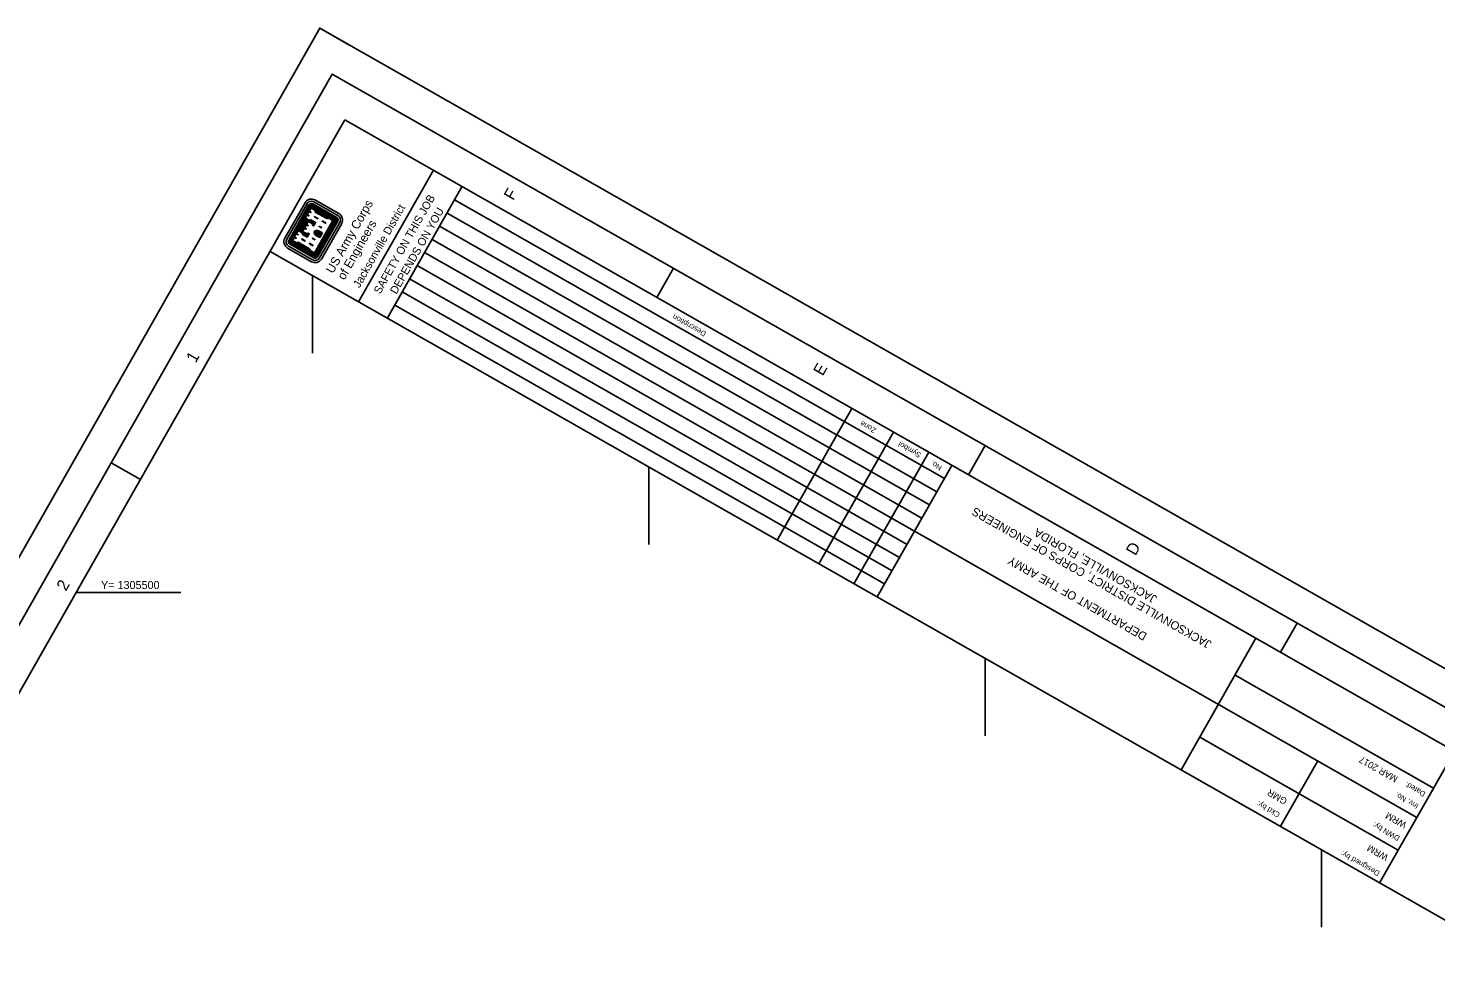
# Model space of a CAD drawing. Extents: x 517335 to 522466, y 1300833 to 1306339.
# Drawn here: x 519077 to 521170, y 1304957 to 1306339 of the extents above; entities that cross this region are included whole.
import ezdxf

# ---------------------------------------------------------------- set-up
doc = ezdxf.new("R2010")
doc.units = 0
for name, color, linetype in [('G-ANNO-NPLT', 7, 'Continuous'), ('G-ANNO-TEXT-DRWG', 7, 'Continuous'), ('G-ANNO-TEXT-LOGO', 7, 'Continuous'), ('G-ANNO-TEXT-PROJ', 7, 'Continuous'), ('G-ANNO-TEXT-TTLB', 7, 'Continuous'), ('G-ANNO-TTLB', 7, 'Continuous'), ('V-TOPO-COOR-STAT', 7, 'Continuous')]:
    doc.layers.add(name, color=color, linetype=linetype)

msp = doc.modelspace()

# ---------------------------------------------------------------- linework, layer by layer
at = {"layer": 'G-ANNO-NPLT'}
msp.add_lwpolyline([(517335, 1302514.1), (519510.6, 1306338.6), (522465.8, 1304657.4), (520290.3, 1300833)], close=True, dxfattribs=at)
msp.add_lwpolyline([(519554, 1306313.8), (519510.6, 1306338.6), (519485.8, 1306295.1)], dxfattribs=at)
at = {"layer": 'G-ANNO-TEXT-LOGO'}
for p, q in [((519488.9, 1306079.2), (519458.8, 1306026.4)), ((519461.6, 1306024.8), (519491.7, 1306077.6)), ((519494.6, 1306076), (519464.6, 1306023.1)), ((519495.4, 1306075.5), (519465.3, 1306022.7)), ((519496.2, 1306075.1), (519466.1, 1306022.2)), ((519496.9, 1306074.7), (519466.8, 1306021.8)), ((519497.7, 1306074.2), (519467.6, 1306021.4)), ((519497.6, 1306072.9), (519532.2, 1306053.2)), ((519498, 1306073.6), (519533.4, 1306053.5)), ((519498.4, 1306074.4), (519534.1, 1306054.1)), ((519498.9, 1306075.1), (519534.5, 1306054.9)), ((519499.3, 1306075.8), (519534.9, 1306055.6)), ((519499.7, 1306076.6), (519535.4, 1306056.3)), ((519500.2, 1306077.4), (519535.8, 1306057.1)), ((519501.8, 1306080.4), (519537.5, 1306060.1)), ((519539.1, 1306063), (519503.5, 1306083.2)), ((519504.9, 1306067.9), (519523, 1306057.6)), ((519505.1, 1306066.7), (519521.7, 1306057.3)), ((519478.7, 1306039.3), (519487.9, 1306055.5)), ((519479.5, 1306038.9), (519488.7, 1306055)), ((519480.2, 1306038.5), (519489.4, 1306054.6)), ((519481, 1306038), (519490.2, 1306054.2)), ((519481.8, 1306037.6), (519491, 1306053.8)), ((519482.5, 1306037.2), (519491.7, 1306053.4)), ((519483.2, 1306036.7), (519492.4, 1306052.9)), ((519532.2, 1306053.2), (519503.3, 1306002.4)), ((519533.4, 1306053.5), (519503.7, 1306001.3)), ((519534.3, 1306053.4), (519504.3, 1306000.5)), ((519535, 1306053), (519505, 1306000.1)), ((519535.8, 1306052.5), (519505.8, 1305999.7)), ((519536.6, 1306052.1), (519506.5, 1305999.2)), ((519537.3, 1306051.7), (519507.2, 1305998.8)), ((519540.3, 1306049.9), (519510.3, 1305997.1)), ((519513.1, 1305995.5), (519543.2, 1306048.3)), ((519510.6, 1306027.3), (519504.8, 1306030.6)), ((519511, 1306028), (519505.2, 1306031.3)), ((519511.5, 1306028.7), (519505.7, 1306032.1)), ((519511.9, 1306029.5), (519506.1, 1306032.8)), ((519512.3, 1306030.2), (519506.5, 1306033.5)), ((519512.9, 1306031.3), (519507.1, 1306034.6)), ((519513.3, 1306032), (519507.5, 1306035.3)), ((519513.8, 1306032.7), (519507.9, 1306036.1)), ((519514.2, 1306033.5), (519508.4, 1306036.8)), ((519514.6, 1306034.2), (519508.8, 1306037.5)), ((519510.6, 1306027.3), (519514.6, 1306034.2)), ((519462.8, 1306011.8), (519498.5, 1305991.5)), ((519500, 1305994.3), (519464.4, 1306014.6)), ((519466.1, 1306017.6), (519501.8, 1305997.3)), ((519466.6, 1306018.4), (519502.2, 1305998.1)), ((519467, 1306019.1), (519502.6, 1305998.8)), ((519467.4, 1306019.9), (519503.1, 1305999.6)), ((519467.9, 1306020.6), (519503.5, 1306000.4)), ((519468.3, 1306021.4), (519503.7, 1306001.3)), ((519468.7, 1306022.1), (519503.3, 1306002.4)), ((519476.6, 1306018.4), (519494.9, 1306008)), ((519477.8, 1306018.8), (519494.4, 1306009.3))]:
    msp.add_line(p, q, dxfattribs=at)
for points in [[(519469.1, 1306022.7), (519475.9, 1306018.8), (519478.2, 1306019.5), (519494.8, 1306010), (519495.6, 1306007.7), (519503.1, 1306003.3), (519531.3, 1306052.9), (519523.8, 1306057.2), (519521.3, 1306056.5), (519504.7, 1306066), (519504.1, 1306068.4), (519497.2, 1306072.3), (519493.5, 1306065.8), (519490.7, 1306060.7), (519488, 1306056), (519494.9, 1306052.1), (519497.3, 1306052.9), (519503.4, 1306049.5), (519501.3, 1306045.8), (519500.7, 1306046.2), (519500, 1306048.6), (519493.2, 1306052.5), (519489.5, 1306046), (519486.6, 1306040.9), (519484, 1306036.3), (519490.8, 1306032.4), (519493.3, 1306033.1), (519493.9, 1306032.8), (519491.8, 1306029.1), (519485.7, 1306032.6), (519485.1, 1306035), (519478.3, 1306038.9), (519474.5, 1306032.4), (519471.7, 1306027.3), (519469.1, 1306022.7)], [(519470.2, 1306023), (519476, 1306019.7), (519478.4, 1306020.4), (519495.6, 1306010.6), (519496.3, 1306008.1), (519502.7, 1306004.5), (519530.1, 1306052.6), (519523.7, 1306056.3), (519521.2, 1306055.5), (519504, 1306065.3), (519503.4, 1306067.9), (519497.6, 1306071.1), (519495, 1306066.4), (519497.7, 1306064.9), (519497.4, 1306064.5), (519494.7, 1306066), (519492.1, 1306061.4), (519494.8, 1306059.9), (519494.6, 1306059.5), (519491.9, 1306061.1), (519489.2, 1306056.4), (519495, 1306053.1), (519497.4, 1306053.8), (519504.5, 1306049.8), (519501.6, 1306044.7), (519499.9, 1306045.7), (519499.3, 1306048.1), (519493.5, 1306051.4), (519490.9, 1306046.7), (519493.5, 1306045.2), (519493.4, 1306044.8), (519490.7, 1306046.3), (519488, 1306041.6), (519490.7, 1306040.1), (519490.4, 1306039.7), (519487.7, 1306041.2), (519485.1, 1306036.6), (519490.9, 1306033.3), (519493.3, 1306034), (519495, 1306033.1), (519492.1, 1306028), (519485.1, 1306032), (519484.4, 1306034.5), (519478.6, 1306037.8), (519476, 1306033.2), (519478.7, 1306031.6), (519478.5, 1306031.2), (519475.8, 1306032.7), (519473.1, 1306028), (519475.8, 1306026.5), (519475.6, 1306026.1), (519472.9, 1306027.7), (519470.2, 1306023)], [(519496.5, 1306051.8), (519497.2, 1306051.9), (519502.1, 1306049.1), (519501.2, 1306047.6), (519500.7, 1306049.2), (519496.4, 1306051.7)], [(519502.8, 1306058.6), (519507.9, 1306055.8), (519507.6, 1306055.3), (519502.6, 1306058.2), (519502.8, 1306058.6)], [(519514.4, 1306052.1), (519519.5, 1306049.1), (519519.3, 1306048.7), (519514.1, 1306051.6), (519514.4, 1306052.1)], [(519483.6, 1306024.8), (519488.6, 1306022), (519488.9, 1306022.5), (519483.9, 1306025.3), (519483.6, 1306024.8)], [(519486.3, 1306033.9), (519486.5, 1306033.2), (519491.5, 1306030.4), (519492.4, 1306032), (519490.6, 1306031.5), (519486.3, 1306034)], [(519499.7, 1306026.2), (519503.3, 1306024.2), (519503.5, 1306024.6), (519499.9, 1306026.7), (519499.7, 1306026.2)], [(519509.9, 1306044.1), (519513.4, 1306042.1), (519513.2, 1306041.7), (519509.6, 1306043.7), (519509.9, 1306044.1)], [(519495.2, 1306018.2), (519500.3, 1306015.3), (519500.6, 1306015.8), (519495.4, 1306018.8), (519495.2, 1306018.2)]]:
    msp.add_lwpolyline(points, dxfattribs=at)
for centre, major_axis, start_param, end_param in [((519498.1, 1306073.9), (5.3, 9.31), 6.283169, 7.853965), ((519498.1, 1306073.9), (3.7, 6.51), 6.28317, 7.853966), ((519498.1, 1306073.9), (1.99, 3.49), 6.283169, 7.853965), ((519498.1, 1306073.9), (1.56, 2.74), 6.283169, 7.853965), ((519498.1, 1306073.9), (1.13, 1.98), 6.283169, 7.853965), ((519498.1, 1306073.9), (0.7, 1.23), 6.283169, 7.853965), ((519498.1, 1306073.9), (0.27, 0.474), 6.283169, 7.853965), ((519533.8, 1306053.6), (0.27, 0.474), 4.712373, 6.28317), ((519533.8, 1306053.6), (0.7, 1.23), 4.712373, 6.28317), ((519533.8, 1306053.6), (1.13, 1.98), 4.712373, 6.28317), ((519533.8, 1306053.6), (1.56, 2.74), 4.712373, 6.28317), ((519533.8, 1306053.6), (1.99, 3.49), 4.712373, 6.28317), ((519533.8, 1306053.6), (-3.7, -6.51), 1.570781, 3.141577), ((519533.8, 1306053.6), (5.3, 9.31), 4.712373, 6.28317), ((519468.1, 1306021.1), (5.3, 9.31), 1.57078, 3.141576), ((519468.1, 1306021.1), (3.7, 6.51), 1.57078, 3.141576), ((519507.9, 1306035.1), (-2.75, -4.83), 4.985832, 6.214359), ((519506.4, 1306032.5), (2.75, 4.83), 0.068795, 1.29842), ((519507.9, 1306035.1), (-2.32, -4.07), 4.947465, 6.21436), ((519506.4, 1306032.5), (2.32, 4.07), 0.068795, 1.335689), ((519506.4, 1306032.5), (1.89, 3.32), 0.068795, 1.335689), ((519507.9, 1306035.1), (-1.89, -3.32), 4.947465, 6.21436), ((519506.4, 1306032.5), (1.46, 2.56), 0.068794, 1.335689), ((519507.9, 1306035.1), (-1.46, -2.56), 4.947465, 6.21436), ((519506.4, 1306032.5), (1.03, 1.81), 0.068794, 1.335689), ((519507.9, 1306035.1), (-1.03, -1.81), 4.947465, 6.214359), ((519468.1, 1306021.1), (1.99, 3.49), 1.57078, 3.141576), ((519468.1, 1306021.1), (1.56, 2.74), 1.57078, 3.141576), ((519468.1, 1306021.1), (1.13, 1.98), 1.57078, 3.141576), ((519468.1, 1306021.1), (0.7, 1.23), 1.57078, 3.141576), ((519468.1, 1306021.1), (0.27, 0.474), 1.57078, 3.141576), ((519503.8, 1306000.8), (-5.3, -9.31), 6.28317, 7.853966), ((519503.8, 1306000.8), (-3.7, -6.51), 6.28317, 7.853966), ((519503.8, 1306000.8), (-1.99, -3.49), 6.28317, 7.853966), ((519503.8, 1306000.8), (-1.56, -2.74), 6.28317, 7.853966), ((519503.8, 1306000.8), (-1.13, -1.98), 6.28317, 7.853966), ((519503.8, 1306000.8), (-0.7, -1.23), 6.28317, 7.853966), ((519503.8, 1306000.8), (-0.27, -0.474), 6.28317, 7.853966)]:
    msp.add_ellipse(centre, major_axis=major_axis, ratio=0.99964, start_param=start_param, end_param=end_param, dxfattribs=at)
at = {"layer": 'G-ANNO-TTLB'}
for p, q in [((519568.2, 1305931.8), (519679.5, 1306127.4)), ((519610.6, 1305907), (519721.9, 1306102.6)), ((519711, 1306083.4), (520439.3, 1305669.1)), ((519699.8, 1306063.8), (520428.2, 1305649.5)), ((519677.6, 1306024.7), (520405.9, 1305610.4)), ((519688.7, 1306044.3), (520417, 1305630)), ((519436.8, 1306006.6), (522218.2, 1304424.4)), ((519666.5, 1306005.2), (520394.8, 1305590.9)), ((519655.3, 1305985.6), (520383.7, 1305571.3)), ((519644.2, 1305966.1), (520372.5, 1305551.8)), ((520036.5, 1305981.9), (520011.8, 1305938.4)), ((519633.1, 1305946.5), (520361.4, 1305532.2)), ((519622, 1305926.9), (520350.3, 1305512.6)), ((520190.6, 1305577.8), (520301.8, 1305773.4)), ((520252.5, 1305542.6), (520363.7, 1305738.2)), ((520500, 1305718.2), (520475.3, 1305674.7)), ((519200.5, 1305692.4), (519244, 1305667.6)), ((520304.6, 1305513), (520415.9, 1305708.5)), ((520339.3, 1305493.3), (520450.5, 1305688.8)), ((521141.7, 1305165.5), (520394.9, 1305591)), ((520394.9, 1305591), (520425.6, 1305573.5)), ((520963.6, 1305454.5), (520938.9, 1305411)), ((520790.8, 1305235.5), (520902.4, 1305431.8)), ((520871.3, 1305377), (521166.5, 1305209.1)), ((521114, 1305116.8), (520818.9, 1305285)), ((521085.8, 1305067.2), (521197.6, 1305263.8)), ((520938.4, 1305151.5), (520994.2, 1305249.5))]:
    msp.add_line(p, q, dxfattribs=at)
for points in [[(520271.6, 1300901.1), (522397.7, 1304638.7), (519529.3, 1306270.4), (517403.2, 1302532.8)], [(519548, 1306202.2), (517508.5, 1302616.7), (520289.9, 1301034.5), (522329.5, 1304620)]]:
    msp.add_lwpolyline(points, close=True, dxfattribs=at)
at = {"layer": 'V-TOPO-COOR-STAT'}
for p, q in [((519500, 1305855.6), (519500, 1305970.6)), ((520000, 1305571.2), (520000, 1305686.2)), ((519303.9, 1305500), (519148.6, 1305500)), ((520500, 1305286.7), (520500, 1305401.8)), ((521000, 1305002.3), (521000, 1305117.4))]:
    msp.add_line(p, q, dxfattribs=at)

# ---------------------------------------------------------------- texts
at = {"layer": 'G-ANNO-TEXT-DRWG'}
for s, p in [('GMR', (520950, 1305192.7)), ('WRM', (521127.6, 1305157.4)), ('WRM', (521100.3, 1305109))]:
    msp.add_text(s, height=10, rotation=150.3667, dxfattribs=at).set_placement(p)
at = {"layer": 'G-ANNO-TEXT-PROJ'}
msp.add_text('MAR 2017', height=10, rotation=150.3667, dxfattribs=at).set_placement((521114.4, 1305225.8))
at = {"layer": 'G-ANNO-TEXT-TTLB'}
for s, height, rotation, p in [('SAFETY ON THIS JOB', 11.9, 60.3667, (519600.5, 1305942.4)), ('US Army Corps', 13.086, 60.3667, (519530.3, 1305972.9)), ('Jacksonville District', 11.9, 60.3667, (519569.7, 1305951.7)), ('DEPENDS ON YOU', 11.9, 60.3667, (519624.5, 1305942.3)), ('of Engineers', 13.086, 60.3667, (519547.2, 1305963.3)), ('Description', 8, 150.3667, (520085.9, 1305886.6)), ('Zone', 8, 150.3667, (520338.7, 1305743.1)), ('Symbol', 8, 150.3667, (520405.6, 1305706.4)), ('No.', 8, 150.3667, (520436.5, 1305687.7)), ('JACKSONVILLE DISTRICT, CORPS OF ENGINEERS', 12.5, 150.3667, (520837.6, 1305426.5)), ('JACKSONVILLE, FLORIDA', 12.5, 150.3667, (520756.5, 1305493.9)), ('DEPARTMENT OF THE ARMY', 12.5, 150.3667, (520741.6, 1305438.5)), ('Dated:', 8, 150.3667, (521155.3, 1305202.8)), ('Ckd by:', 8, 150.3667, (520939.1, 1305171.9)), ('Inv. No.', 8, 150.3667, (521145.1, 1305184.7)), ('DWN by:', 8, 150.3667, (521117.2, 1305137.1)), ('Designed by:', 8, 150.3667, (521087.4, 1305084.7))]:
    msp.add_text(s, height=height, rotation=rotation, dxfattribs=at).set_placement(p)
at = {"layer": 'G-ANNO-TTLB'}
for s, p in [('F', (519798.4, 1306081.4)), ('1', (519326.1, 1305840)), ('E', (520258.4, 1305820.6)), ('D', (520723.3, 1305553.6)), ('2', (519133.3, 1305501))]:
    msp.add_text(s, height=17.5, rotation=60.3667, dxfattribs=at).set_placement(p)
at = {"layer": 'V-TOPO-COOR-STAT'}
msp.add_text('Y= 1305500', height=12, dxfattribs=at).set_placement((519185.5, 1305505))

doc.saveas('drawing.dxf')
